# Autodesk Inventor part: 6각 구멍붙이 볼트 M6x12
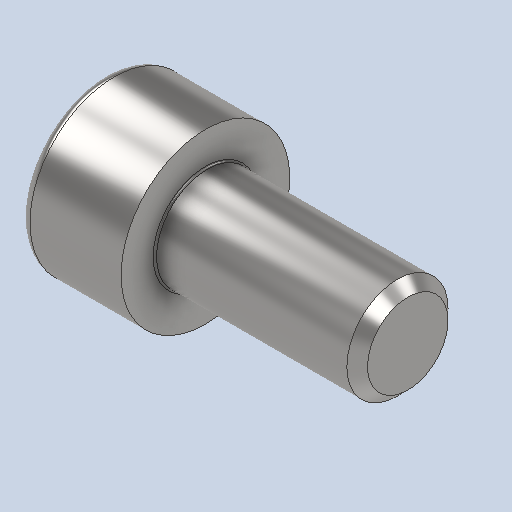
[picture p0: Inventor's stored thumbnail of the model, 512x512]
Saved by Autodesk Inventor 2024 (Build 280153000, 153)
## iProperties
Created: 2025-05
Part Number: 6각 구멍붙이 볼트 M6x12
Material: 강철, 연강
Description: 6각머리 태핑 나사
Document SubType Name: Modeling
Designer: 11
Density: 7.85 g/cm^3
Appearance: 기본값
Author: jhkim
Sending System: Autodesk Inventor 2026
Preprocessor: ST-DEVELOPER v20.1
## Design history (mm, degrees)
node "6각 구멍붙이 볼트 M6x121"
node "솔리드1"
body "Solid1"
